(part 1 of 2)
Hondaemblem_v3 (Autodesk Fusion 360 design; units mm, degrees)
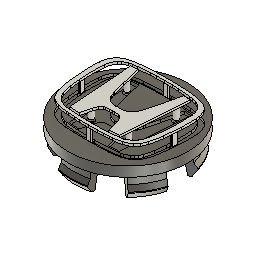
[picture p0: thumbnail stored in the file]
canvas "Ansichtsbereich"
sketch "Skizze1" plane through (0, 0, 0) normal (0, 0, 1) x axis (1, 0, 0)
  line L1 (14.7403, 16.2796) -> (11.3697, 16.5909)
  line L2 (9.2155, 7.0997) -> (11.3697, 16.5909)
  line L3 (7.6397, 1.1797) -> (9.2155, 7.0997)
  line L4 (7.4453, 0.4535) -> (7.6397, 1.1797)
  line L5 (1.2661, -4.9077) -> (0.003, -4.9077)
  line L6 (12.3974, -16.7274) -> (14.7403, 16.2796)
  line L7 (7.491, -17.0185) -> (12.3974, -16.7274)
  line L8 (1.2876, -7.8245) -> (0.011, -7.8245)
  line L9 (7.491, -17.0185) -> (6.1505, -11.8495)
  line L10 (0.011, -7.8245) -> (0.003, -4.9077)
  line L11 (1.489, -18.363) -> (0.0029, -18.3671)
  line L12 (1.489, -18.363) -> (0.0029, -18.3671)
  line L13 (1.7175, 19.8498) -> (-0.0237, 19.8498)
  line L14 (7.2522, -19.7275) -> (10.1907, -19.5091)
  line L15 (-7.418, -17.0597) -> (-6.1061, -11.8834)
  line L16 (-7.4689, 0.4122) -> (-7.6673, 1.1374)
  line L17 (-7.1642, -19.7674) -> (-10.1039, -19.5652)
  line L18 (-14.8513, 16.1978) -> (-11.4824, 16.5277)
  line L19 (-9.2758, 7.0486) -> (-11.4824, 16.5277)
  line L20 (-7.418, -17.0597) -> (-12.3259, -16.7957)
  line L21 (-7.6673, 1.1374) -> (-9.2758, 7.0486)
  line L22 (-12.3259, -16.7957) -> (-14.8513, 16.1978)
  line L23 (-1.4087, -18.371) -> (0.0774, -18.3669)
  line L24 (-1.2655, -7.8316) -> (0.011, -7.8245)
  line L25 (-1.2602, -4.9147) -> (0.003, -4.9077)
  line L26 (-1.8484, 19.84) -> (-0.1072, 19.8496)
  line L27 (-0.0665, -18.3673) -> (0.0774, -18.3669)
  line L28 (0.1112, -19.955) -> (-0.0002, -19.9555)
  line L29 (0, 18.41) -> (-0.123, 18.4097)
  line L30 (-0.1072, 19.8496) -> (-0.0237, 19.8498)
  line L31 (-0.0676, -17.9673) -> (0.0763, -17.9669)
  line L32 (1.2629, -4.7077) -> (0.0024, -4.7077)
  line L33 (7.2521, 0.5052) -> (7.4465, 1.2313)
  line L34 (7.4465, 1.2313) -> (9.0212, 7.1476)
  line L35 (9.0212, 7.1476) -> (11.2135, 16.8061)
  line L36 (14.9536, 16.4608) -> (11.2135, 16.8061)
  line L37 (12.5844, -16.9167) -> (14.9536, 16.4608)
  line L38 (7.3386, -17.2279) -> (12.5844, -16.9167)
  line L39 (7.3386, -17.2279) -> (5.9566, -11.8986)
  line L40 (1.2876, -8.0245) -> (0.0116, -8.0245)
  line L41 (-1.2644, -8.0316) -> (0.0116, -8.0245)
  line L42 (-7.2645, -17.2683) -> (-5.9119, -11.9314)
  line L43 (-7.2645, -17.2683) -> (-12.5119, -16.986)
  line L44 (-12.5119, -16.986) -> (-15.0656, 16.3778)
  line L45 (-15.0656, 16.3778) -> (-11.3274, 16.7438)
  line L46 (-9.0818, 7.0975) -> (-11.3274, 16.7438)
  line L47 (-7.4744, 1.1901) -> (-9.0818, 7.0975)
  line L48 (-7.276, 0.465) -> (-7.4744, 1.1901)
  line L49 (-1.258, -4.7147) -> (0.0024, -4.7077)
  line L50 (-0.066, -18.5673) -> (0.078, -18.5669)
  line L51 (0.0023, -18.1671) -> (0.0769, -18.1669)
  line L52 (-1.4092, -18.171) -> (0.0023, -18.1671)
  line L53 (-0.0028, 18.21) -> (-0.1191, 18.2097)
  line L54 (1.4884, -18.163) -> (0.0769, -18.1669)
  line L55 (7.267, -19.927) -> (10.2055, -19.7085)
  line L56 (1.7175, 20.0498) -> (-0.024, 20.0498)
  line L57 (-0.108, 20.0496) -> (-0.024, 20.0498)
  line L58 (-1.8495, 20.04) -> (-0.108, 20.0496)
  line L59 (-7.178, -19.9669) -> (-10.1176, -19.7647)
  arc A1 centre (-5.6033, 3.9463) radius 13.508 clockwise from (7.4453, 0.4535) to (6.6276, -1.787)
  arc A2 centre (1.7719, 0.4891) radius 5.3627 clockwise from (6.6276, -1.787) to (2.178, -4.8581)
  arc A3 centre (0.569, 16.3289) radius 21.248 clockwise from (2.178, -4.8581) to (1.2661, -4.9077)
  arc A4 centre (1.2876, -19.9561) radius 12.1316 clockwise from (1.2876, -7.8245) to (3.2582, -7.9857)
  arc A5 centre (2.9272, -9.9961) radius 2.0375 clockwise from (3.2582, -7.9857) to (4.0649, -8.3058)
  arc A6 centre (2.0068, -11.3638) radius 3.6861 clockwise from (4.0649, -8.3058) to (5.1675, -9.4672)
  arc A7 centre (-2.2698, -13.9299) radius 8.6734 clockwise from (5.1675, -9.4672) to (6.1505, -11.8495)
  arc A8 centre (1.224, 77.5099) radius 95.8732 clockwise from (13.5076, -17.5732) to (1.489, -18.363)
  arc A9 centre (12.7513, -11.7186) radius 5.9032 clockwise from (15.05, -17.1559) to (13.5076, -17.5732)
  arc A10 centre (8.9082, -2.6284) radius 15.7724 clockwise from (17.37, -15.9388) to (15.05, -17.1559)
  arc A11 centre (15.2799, -12.6511) radius 3.8959 clockwise from (18.3081, -15.1021) to (17.37, -15.9388)
  arc A12 centre (-1.4919, 0.9237) radius 25.4728 clockwise from (19.2556, -13.855) to (18.3081, -15.1021)
  arc A13 centre (14.4543, -10.4349) radius 5.8949 clockwise from (20.0596, -12.2596) to (19.2556, -13.855)
  arc A14 centre (-8.1428, -3.079) radius 29.659 clockwise from (21.1576, -7.6773) to (20.0596, -12.2596)
  arc A15 centre (-50.9109, 3.633) radius 72.9507 clockwise from (21.8058, -2.2052) to (21.1576, -7.6773)
  arc A16 centre (-55.8755, 4.0316) radius 77.9312 clockwise from (21.8058, 10.2685) to (21.8058, -2.2052)
  arc A17 centre (13.0733, 9.5674) radius 8.7605 clockwise from (19.9777, 14.9596) to (21.8058, 10.2685)
  arc A18 centre (16.9965, 12.6313) radius 3.7827 clockwise from (18.947, 15.8723) to (19.9777, 14.9596)
  arc A19 centre (12.8299, 5.7077) radius 11.8633 clockwise from (16.6863, 16.9267) to (18.947, 15.8723)
  arc A20 centre (3.8353, -18.6888) radius 37.0384 clockwise from (3.8143, 18.3497) to (6.8105, 18.23)
  arc A21 centre (13.0764, 6.4248) radius 11.105 clockwise from (15.0535, 17.3524) to (16.6863, 16.9267)
  arc A22 centre (8.3657, -19.6124) radius 37.5649 clockwise from (12.8326, 17.686) to (15.0535, 17.3524)
  arc A23 centre (0.4785, -85.4698) radius 103.8929 clockwise from (6.8105, 18.23) to (12.8326, 17.686)
  arc A24 centre (3.7437, 142.9454) radius 124.5958 clockwise from (3.8143, 18.3497) to (-0.123, 18.4097)
  arc A25 centre (13.0733, 9.5674) radius 8.7605 clockwise from (19.9777, 14.9596) to (21.8058, 10.2685)
  arc A26 centre (8.9082, -2.6284) radius 15.7724 clockwise from (17.37, -15.9388) to (15.05, -17.1559)
  arc A27 centre (16.9965, 12.6313) radius 3.7827 clockwise from (18.947, 15.8723) to (19.9777, 14.9596)
  arc A28 centre (12.8299, 5.7077) radius 11.8633 clockwise from (16.6863, 16.9267) to (18.947, 15.8723)
  arc A29 centre (13.0764, 6.4248) radius 11.105 clockwise from (15.0535, 17.3524) to (16.6863, 16.9267)
  arc A30 centre (-55.8755, 4.0316) radius 77.9312 clockwise from (21.8058, 10.2685) to (21.8058, -2.2052)
  arc A31 centre (15.2799, -12.6511) radius 3.8959 clockwise from (18.3081, -15.1021) to (17.37, -15.9388)
  arc A32 centre (-8.1428, -3.079) radius 29.659 clockwise from (21.1576, -7.6773) to (20.0596, -12.2596)
  arc A33 centre (-50.9109, 3.633) radius 72.9507 clockwise from (21.8058, -2.2052) to (21.1576, -7.6773)
  arc A34 centre (-1.4919, 0.9237) radius 25.4728 clockwise from (19.2556, -13.855) to (18.3081, -15.1021)
  arc A35 centre (14.4543, -10.4349) radius 5.8949 clockwise from (20.0596, -12.2596) to (19.2556, -13.855)
  arc A36 centre (12.7513, -11.7186) radius 5.9032 clockwise from (15.05, -17.1559) to (13.5076, -17.5732)
  arc A37 centre (1.224, 77.5099) radius 95.8732 clockwise from (13.5076, -17.5732) to (1.489, -18.363)
  arc A38 centre (8.3657, -19.6124) radius 37.5649 clockwise from (12.8326, 17.686) to (15.0535, 17.3524)
  arc A39 centre (0.4785, -85.4698) radius 103.8929 clockwise from (6.8745, 18.2261) to (12.8326, 17.686)
  arc A40 centre (3.8353, -18.6888) radius 37.0397 clockwise from (3.8353, 18.351) to (6.8745, 18.2261)
  arc A41 centre (3.8353, 142.9437) radius 124.5927 clockwise from (3.8353, 18.351) to (0, 18.41)
  arc A42 centre (1.7175, -96.317) radius 116.1669 clockwise from (1.7175, 19.8498) to (11.6229, 19.4267)
  arc A43 centre (7.8992, -24.0836) radius 43.6694 clockwise from (11.6229, 19.4267) to (17.105, 18.6044)
  arc A44 centre (14.7144, 7.5187) radius 11.3406 clockwise from (17.105, 18.6044) to (21.4708, 16.6269)
  arc A45 centre (19.0969, 13.4267) radius 3.9846 clockwise from (21.4708, 16.6269) to (22.4141, 15.6341)
  arc A46 centre (12.4351, 8.9937) radius 11.9865 clockwise from (22.4141, 15.6341) to (24.1926, 11.3252)
  arc A47 centre (14.2774, 9.359) radius 10.1083 clockwise from (24.1926, 11.3252) to (24.3555, 10.1404)
  arc A48 centre (-27.9737, 6.0834) radius 52.4862 clockwise from (24.3555, 10.1404) to (24.373, 2.259)
  arc A49 centre (-312.3688, 26.8612) radius 337.6393 clockwise from (24.373, 2.259) to (23.6781, -5.8921)
  arc A50 centre (-7.6057, -2.843) radius 31.432 clockwise from (23.6781, -5.8921) to (22.3695, -12.3014)
  arc A51 centre (6.3134, -7.2351) radius 16.8364 clockwise from (22.3695, -12.3014) to (21.3014, -14.9047)
  arc A52 centre (16.2941, -12.3424) radius 5.6248 clockwise from (21.3014, -14.9047) to (19.4858, -16.974)
  arc A53 centre (12.2327, -6.4486) radius 12.7824 clockwise from (19.4858, -16.974) to (15.8012, -18.7229)
  arc A54 centre (10.7069, -1.2005) radius 18.2479 clockwise from (15.8012, -18.7229) to (11.5158, -19.4304)
  arc A55 centre (13.486, -63.8389) radius 44.4521 clockwise from (10.1907, -19.5091) to (11.5158, -19.4304)
  arc A56 centre (2.7253, 41.1689) radius 61.0644 clockwise from (7.2522, -19.7275) to (4.4477, -19.8712)
  arc A57 centre (-2.435, 224.0452) radius 244.0136 clockwise from (4.4477, -19.8712) to (0.0029, -19.9561)
  arc A58 centre (-14.4176, -10.5147) radius 5.8949 clockwise from (-19.1999, -13.9613) to (-20.0127, -12.3704)
  arc A59 centre (-3.7531, -18.7097) radius 37.0384 clockwise from (-6.9324, 18.192) to (-3.9369, 18.3282)
  arc A60 centre (-17.0873, 12.5371) radius 3.7827 clockwise from (-20.0813, 14.8488) to (-19.0556, 15.7673)
  arc A61 centre (-0.0273, -85.4712) radius 103.8929 clockwise from (-12.9514, 17.6147) to (-6.9964, 18.1877)
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  point P261 (-0.0665, -18.3673)
  point P263 (0.1112, -19.955)
  tangent L4 A1
  tangent A1 A2
  horizontal L5
  tangent A2 A3
  horizontal L8
  tangent L8 A4
  tangent A4 A5
  tangent A5 A6
  tangent A6 A7
  perpendicular L10 L11
  tangent L11 A8
  tangent A8 A9
  tangent A9 A10
  tangent A10 A11
  tangent A11 A12
  tangent A12 A13
  tangent A13 A14
  tangent A14 A15
  tangent A15 A16
  tangent A16 A17
  tangent A17 A18
  tangent A18 A19
  tangent A19 A21
  tangent A21 A22
  tangent A22 A23
  tangent A20 A24
  tangent A37 L12
  tangent A36 A37
  tangent A26 A36
  tangent A26 A31
  tangent A31 A34
  tangent A34 A35
  tangent A32 A35
  tangent A32 A33
  tangent A30 A33
  tangent A25 A30
  tangent A25 A27
  tangent A27 A28
  tangent A28 A29
  tangent A29 A38
  tangent A38 A39
  tangent A40 A41
  horizontal L13
  tangent L13 A42
  tangent A42 A43
  tangent A43 A44
  tangent A44 A45
  tangent A45 A46
  tangent A46 A47
  tangent A47 A48
  tangent A48 A49
  tangent A49 A50
  tangent A50 A51
  tangent A51 A52
  tangent A52 A53
  tangent A53 A54
  tangent A54 A55
  tangent L14 A56
  tangent A56 A57
  coincident L23 P261
  coincident A57 P263
  parallel L27 L31
  parallel L27 L50
  parallel L23 L51
  parallel L23 L52
  parallel L29 L53
  parallel L12 L54
  dimension "d174" = -0.2
  dimension "d176" = 0.2
  dimension "d177" = 0.2
  dimension "d178" = 0.2
extrude "Extrusion1" new body sketch "Skizze1" along normal blind 2
sketch "Skizze2" plane through (0, 0, 0) normal (0, 0, 1) x axis (1, 0, 0)
  circle C1 centre (0, 0) radius 30
  circle C2 centre (0, 0) radius 29
  point P1 (0, 0)
  point P2 (0, 0)
  coincident P1 P2
  concentric C1 C2
  dimension "d3" diameter C1 = 60
  dimension "d11" diameter C2 = 58
extrude "Extrusion4" add sketch "Skizze2" along normal blind 1
extrude "Extrusion5" add sketch "Skizze2" along normal blind 2
extrude "Extrusion6" cut of existing geometry blind -1
sketch "Skizze4" plane through (0, 0, 1) normal (0, 0, 1) x axis (-1, 0, 0)
  line L1 (-7.2522, 19.7275) -> (-10.1907, 19.5091)
  line L2 (0.0002, 19.9555) -> (-0.1112, 19.955)
  line L3 (10.1039, 19.5652) -> (7.1642, 19.7674)
  line L4 (0.1072, -19.8496) -> (1.8484, -19.84)
  line L5 (0.0237, -19.8498) -> (0.1072, -19.8496)
  line L6 (-1.7175, -19.8498) -> (0.0237, -19.8498)
  circle C1 centre (0, 0) radius 30
  arc A1 centre (-13.486, 63.8389) radius 44.4521 clockwise from (-10.1907, 19.5091) to (-11.5158, 19.4304)
  arc A2 centre (-2.7253, -41.1689) radius 61.0644 clockwise from (-7.2522, 19.7275) to (-4.4477, 19.8712)
  arc A3 centre (2.435, -224.0452) radius 244.0136 clockwise from (-4.4477, 19.8712) to (-0.1112, 19.955)
  arc A4 centre (-1.1752, -224.0552) radius 244.0136 clockwise from (0.0002, 19.9555) to (4.359, 19.8956)
  arc A5 centre (2.974, -41.1531) radius 61.0644 clockwise from (4.359, 19.8956) to (7.1642, 19.7674)
  arc A6 centre (13.1541, 63.9125) radius 44.4521 clockwise from (11.4294, 19.4939) to (10.1039, 19.5652)
  arc A7 centre (10.7214, 1.2597) radius 18.2479 clockwise from (11.4294, 19.4939) to (15.7186, 18.81)
  arc A8 centre (12.2181, 6.5162) radius 12.7824 clockwise from (15.7186, 18.81) to (19.4129, 17.0815)
  arc A9 centre (16.2469, 12.4323) radius 5.6248 clockwise from (19.4129, 17.0815) to (21.2399, 15.0223)
  arc A10 centre (6.2945, 7.2699) radius 16.8364 clockwise from (21.2399, 15.0223) to (22.3223, 12.425)
  arc A11 centre (-7.6001, 2.801) radius 31.432 clockwise from (22.3223, 12.425) to (23.6664, 6.023)
  arc A12 centre (-312.1943, -28.5875) radius 337.6393 clockwise from (23.6664, 6.023) to (24.4063, -2.1242)
  arc A13 centre (-27.9185, -6.2379) radius 52.4862 clockwise from (24.4063, -2.1242) to (24.4324, -10.0055)
  arc A14 centre (14.3501, -9.2799) radius 10.1083 clockwise from (24.4324, -10.0055) to (24.2761, -11.1912)
  arc A15 centre (12.5058, -8.9248) radius 11.9865 clockwise from (24.2761, -11.1912) to (22.5214, -15.5099)
  arc A16 centre (19.192, -13.3209) radius 3.9846 clockwise from (22.5214, -15.5099) to (21.5836, -16.5079)
  arc A17 centre (14.7769, -7.4372) radius 11.3406 clockwise from (21.5836, -16.5079) to (17.2288, -18.5095)
  arc A18 centre (7.7872, 24.127) radius 43.6694 clockwise from (17.2288, -18.5095) to (11.7513, -19.3621)
  arc A19 centre (1.2062, 96.3251) radius 116.1669 clockwise from (11.7513, -19.3621) to (1.8484, -19.84)
  arc A20 centre (-1.7175, 96.317) radius 116.1669 clockwise from (-1.7175, -19.8498) to (-11.6229, -19.4267)
  arc A21 centre (-7.8992, 24.0836) radius 43.6694 clockwise from (-11.6229, -19.4267) to (-17.105, -18.6044)
  arc A22 centre (-14.7144, -7.5187) radius 11.3406 clockwise from (-17.105, -18.6044) to (-21.4708, -16.6269)
  arc A23 centre (-19.0969, -13.4267) radius 3.9846 clockwise from (-21.4708, -16.6269) to (-22.4141, -15.6341)
  arc A24 centre (-12.4351, -8.9937) radius 11.9865 clockwise from (-22.4141, -15.6341) to (-24.1926, -11.3252)
  arc A25 centre (-14.2774, -9.359) radius 10.1083 clockwise from (-24.1926, -11.3252) to (-24.3555, -10.1404)
  arc A26 centre (27.9737, -6.0834) radius 52.4862 clockwise from (-24.3555, -10.1404) to (-24.373, -2.259)
  arc A27 centre (312.3688, -26.8612) radius 337.6393 clockwise from (-24.373, -2.259) to (-23.6781, 5.8921)
  arc A28 centre (7.6057, 2.843) radius 31.432 clockwise from (-23.6781, 5.8921) to (-22.3695, 12.3014)
  arc A29 centre (-6.3134, 7.2351) radius 16.8364 clockwise from (-22.3695, 12.3014) to (-21.3014, 14.9047)
  arc A30 centre (-16.2941, 12.3424) radius 5.6248 clockwise from (-21.3014, 14.9047) to (-19.4858, 16.974)
  arc A31 centre (-12.2327, 6.4486) radius 12.7824 clockwise from (-19.4858, 16.974) to (-15.8012, 18.7229)
  arc A32 centre (-10.7069, 1.2005) radius 18.2479 clockwise from (-15.8012, 18.7229) to (-11.5158, 19.4304)
  circle C2 centre (0, 0) radius 29.1
  concentric C1 C2
  dimension "d23" diameter C2 = 58.2
extrude "Extrusion9" cut sketch "Skizze4" profile of C1 C2 against normal blind 1
extrude "Extrusion10" add sketch "Skizze2" along normal blind 1
sketch "Skizze5" plane through (0, 0, 0) normal (0, 0, -1) x axis (1, 0, 0)
  line L1 (-26, 0) -> (-27, 0)
  line L2 (-29.6, 0) -> (-26, 0)
  line L3 (-26, 7.2801) -> (-26, 0)
  line L4 (-26, -7.2801) -> (-26, 0)
  line L5 (-34, -7.2801) -> (-26, -7.2801)
  line L6 (-34, 7.2801) -> (-26, 7.2801)
  line L7 (0, -12) -> (0, 0)
  line L8 (0, 0) -> (0, -12)
  line L9 (0, 0) -> (12, 0)
  line L10 (11, -11) -> (0, 0)
  line L11 (-8.2916, -8.2916) -> (0, 0)
  line L12 (34, 7.2801) -> (26, 7.2801)
  line L13 (26, 7.2801) -> (26, 0)
  line L14 (26, -7.2801) -> (26, 0)
  line L15 (34, -7.2801) -> (26, -7.2801)
  line L16 (-7.2801, -34) -> (-7.2801, -26)
  line L17 (-7.2801, -26) -> (0, -26)
  line L18 (7.2801, -26) -> (0, -26)
  line L19 (7.2801, -34) -> (7.2801, -26)
  line L20 (-7.2801, 34) -> (-7.2801, 26)
  line L21 (-7.2801, 26) -> (0, 26)
  line L22 (7.2801, 34) -> (7.2801, 26)
  line L23 (7.2801, 26) -> (0, 26)
  line L24 (-18.8938, -29.1894) -> (-13.237, -23.5326)
  line L25 (-13.237, -23.5326) -> (-18.3848, -18.3848)
  line L26 (-29.1894, -18.8938) -> (-23.5326, -13.237)
  line L27 (-23.5326, -13.237) -> (-18.3848, -18.3848)
  line L28 (29.1894, -18.8938) -> (23.5326, -13.237)
  line L29 (23.5326, -13.237) -> (18.3848, -18.3848)
  line L30 (18.8938, -29.1894) -> (13.237, -23.5326)
  line L31 (13.237, -23.5326) -> (18.3848, -18.3848)
  line L32 (-18.8938, 29.1894) -> (-13.237, 23.5326)
  line L33 (-13.237, 23.5326) -> (-18.3848, 18.3848)
  line L34 (-29.1894, 18.8938) -> (-23.5326, 13.237)
  line L35 (-23.5326, 13.237) -> (-18.3848, 18.3848)
  line L36 (29.1894, 18.8938) -> (23.5326, 13.237)
  line L37 (23.5326, 13.237) -> (18.3848, 18.3848)
  line L38 (18.8938, 29.1894) -> (13.237, 23.5326)
  line L39 (13.237, 23.5326) -> (18.3848, 18.3848)
  circle C1 centre (0, 0) radius 30
  circle C2 centre (0, 0) radius 27
  circle C3 centre (0, 0) radius 27.7
  circle C4 centre (0, 0) radius 29.6
  circle C5 centre (0, 0) radius 28
  point P5 (-27, 0)
  point P8 (-26, 7.2801)
  point P9 (-26, -7.2801)
  point P7 (-29.6, 0)
  point P13 (0, 0)
  point P14 (0, 0)
  point P12 (0, 0)
  point P16 (0, 0)
  point P3 (0, 0)
  point P18 (0, 0)
  point P20 (0, 0)
  point P6 (-26, 0)
  point P24 (26, 0)
  point P22 (26, 7.2801)
  point P25 (26, -7.2801)
  point P10 (-34, -7.2801)
  point P26 (34, -7.2801)
  point P11 (-34, 7.2801)
  point P23 (34, 7.2801)
  point P34 (0, 26)
  point P32 (-7.2801, 26)
  point P35 (7.2801, 26)
  point P36 (7.2801, 34)
  point P33 (-7.2801, 34)
  point P27 (-7.2801, -26)
  point P28 (-7.2801, -34)
  point P29 (0, -26)
  point P30 (7.2801, -26)
  point P31 (7.2801, -34)
  concentric C1 C2
  coincident C2 P5
  horizontal L1
  coincident C2 P8
  perpendicular L1 L3
  coincident C2 P9
  perpendicular L1 L4
  perpendicular L4 L5
  perpendicular L3 L6
  concentric C2 C4
  coincident P7 C4
  concentric C4 C5
  coincident P13 P14
  vertical L7
  coincident P12 P16
  parallel L7 L8
  perpendicular L7 L9
  coincident P3 P18
  coincident P3 P20
  perpendicular L10 L11
  symmetric P6 L8 P24
  symmetric P8 L8 P22
  symmetric P9 L8 P25
  symmetric P10 L8 P26
  symmetric P11 L8 P23
  symmetric P6 L10 P34
  symmetric P8 L10 P32
  symmetric P9 L10 P35
  symmetric P10 L10 P36
  symmetric P11 L10 P33
  symmetric L10 P22 P27
  symmetric L10 P23 P28
  symmetric L10 P24 P29
  symmetric L10 P25 P30
  symmetric L10 P26 P31
  perpendicular L34 L35
  perpendicular L32 L33
  dimension "d33" diameter C2 = 54
  dimension "d35" diameter C3 = 55.4 (= "53.000 mm + 2.4 mm")
  dimension "d36" distance P5 P6 = 1
  dimension "d37" distance P6 P7 = 3.6
  dimension "d38" diameter C5 = 56
extrude "Extrusion11" add sketch "Skizze5" profile of C2 C3 L3 L4 L5 L6 C5 L12 L13 L14 L15 L16 L17 L18 L19 L20 L21 L22 L23 L24 L25 L26 L27 L28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 along normal blind 4.6
extrude "Extrusion12" sketch "Skizze5" profile of C2 C3 L3 L4 L5 L6 C4 C5 L12 L13 L14 L15 L16 L17 L18 L19 L20 L21 L22 L23 L24 L25 L26 L27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 blind 5
sketch "Skizze6" plane through (0, -7.2801, 0) normal (0, -1, 0) x axis (1, 0, 0)
  line L1 (-27.037, 0) -> (-26, 0)
  line L2 (-27.037, -4.6) -> (-27.037, 0)
  line L3 (-28.6908, -4.6) -> (-27.037, -4.6)
  line L4 (-28.6908, -9.6) -> (-28.6908, -4.6)
  line L5 (-26, -9.6) -> (-28.6908, -9.6)
  line L6 (-26, 0) -> (-26, -9.6)
  line L7 (-28.5813, -7.2655) -> (-27.037, -9.6)
  line L8 (-27.037, -4.6) -> (-28.5813, -6.9345)
  line L9 (-27.037, -9.6) -> (-26, -9.6)
  line L10 (-26, -4.6) -> (-27.037, -4.6)
  line L11 (-26, -9.6) -> (-26, -4.6)
  arc A1 centre (-28.3311, -7.1) radius 0.3 clockwise from (-28.5813, -7.2655) to (-28.5813, -6.9345)
  point P4 (-27.037, -4.6)
  point P8 (-27.037, -4.6)
  point P12 (-27.037, -4.6)
  point P7 (-26, -9.6)
  point P10 (-26, -9.6)
  coincident P4 P8
  horizontal L9
  horizontal L10
  vertical L11
  coincident P4 P12
  coincident P7 P10
  tangent L7 A1
  tangent L8 A1
  dimension "d44" radius A1 = 0.3
chamfer "Fase1" distance 1.6 Rotate Angle 57.5
chamfer "Fase2" distance 1.6 Rotate Angle 57
delete_face "Fläche löschen2"
fillet "Abrundung2" radius 0.4
work_plane "Arbeitsebene1" AlongDistance 0
split "Teilen1" bodies "Emblem"
move "Verschieben1"
extrude "Extrusion13" add of existing geometry blind 2
sketch "Skizze8" plane through (0, 0, -2) normal (0, 0, -1) x axis (1, 0, 0)
  circle C1 centre (0, 0) radius 30
  circle C2 centre (0, 0) radius 27
  circle C3 centre (0, 0) radius 28
  point P1 (0, 0)
  point P4 (0, 0)
  coincident P1 P4
fillet "Abrundung3" radius 0.4
combine "Kombinieren1"
extrude "Extrusion14" add of existing geometry blind 1
extrude "Extrusion16" add of existing geometry blind 1
extrude "Extrusion17" add of existing geometry blind 1
extrude "Extrusion18" add of existing geometry blind 1
extrude "Extrusion19" add of existing geometry blind 1
extrude "Extrusion20" add of existing geometry blind 1
work_plane "Arbeitsebene2" AlongDistance 0
split "Teilen2" bodies "Emblem (1)", "Emblem (2)", "Emblem (3)", "Emblem (4)", "Emblem (5)", "Emblem (6)", "Emblem (7)", "Emblem (8)"
sketch "Skizze9" plane through (0, 0, -2) normal (0, 0, -1) x axis (1, 0, 0)
  line L1 (0, 30) -> (0, 0)
  line L2 (25.9808, 15) -> (0, 0)
  line L3 (25.9808, -15) -> (0, 0)
  line L4 (0, -30) -> (0, 0)
  line L5 (-25.9808, -15) -> (0, 0)
  line L6 (-25.9808, 15) -> (0, 0)
  circle C1 centre (0, 0) radius 30
  circle C2 centre (0, 0) radius 30
  circle C3 centre (0, 0) radius 30
  point P1 (0, 0)
  point P3 (0, 0)
  point P4 (0, 0)
  point P5 (0, 0)
  point P6 (0, 30)
  point P7 (0, 0)
  point P8 (25.9808, 15)
  point P9 (0, 0)
  point P10 (25.9808, -15)
  point P11 (0, 0)
  point P12 (0, -30)
  point P15 (0, 0)
  point P16 (-25.9808, 15)
  point P13 (0, 0)
  point P14 (-25.9808, -15)
  coincident P1 P3
  coincident P1 P4
  coincident P4 P5
  coincident C2 P6
  vertical L1
  coincident P1 P7
  coincident C3 P8
  coincident P4 P9
  coincident C3 P10
  coincident P3 P11
  coincident C3 P12
  parallel L1 L4
  symmetric L1 P7 P15
  symmetric L1 P8 P16
  symmetric L1 P9 P13
  symmetric L1 P10 P14
  dimension "d72" angle L1 L2 = 60
  dimension "d73" angle L2 L3 = 60
move "Verschieben2"
copy_paste_bodies "Körper kopieren/einfügen"
move "Verschieben3"
combine "Kombinieren2" bodies "Emblem (6) (1)", "Emblem (2)", "Emblem (5)", "Emblem (6)", "Emblem (7)", "Emblem"
chamfer "Fase3" distance 3
sketch "Skizze10" plane through (0, 0, 2) normal (0, 0, 1) x axis (-1, 0, 0)
  line L1 (-0.003, 4.9077) -> (-1.2661, 4.9077)
  line L2 (1.2602, 4.9147) -> (-0.003, 4.9077)
  line L3 (7.6673, -1.1374) -> (7.4689, -0.4122)
  line L4 (9.2758, -7.0486) -> (7.6673, -1.1374)
  line L5 (11.4824, -16.5277) -> (9.2758, -7.0486)
  line L6 (14.8513, -16.1978) -> (11.4824, -16.5277)
  line L7 (12.3259, 16.7957) -> (14.8513, -16.1978)
  line L8 (7.418, 17.0597) -> (12.3259, 16.7957)
  line L9 (6.1061, 11.8834) -> (7.418, 17.0597)
  line L10 (-0.011, 7.8245) -> (1.2655, 7.8316)
  line L11 (-1.2876, 7.8245) -> (-0.011, 7.8245)
  line L12 (-7.491, 17.0185) -> (-6.1505, 11.8495)
  line L13 (-12.3974, 16.7274) -> (-7.491, 17.0185)
  line L14 (-14.7403, -16.2796) -> (-12.3974, 16.7274)
  line L15 (-11.3697, -16.5909) -> (-14.7403, -16.2796)
  line L16 (-9.2155, -7.0997) -> (-11.3697, -16.5909)
  line L17 (-7.6397, -1.1797) -> (-9.2155, -7.0997)
  line L18 (-7.4453, -0.4535) -> (-7.6397, -1.1797)
  line L19 (9.5555, 3.6264) -> (13.1668, -16.3628)
  line L20 (-0.011, 7.8245) -> (-0.003, 4.9077)
  line L21 (9, 3) -> (9.8719, 16.9277)
  arc A1 centre (0.6805, -16.3254) radius 21.248 clockwise from (1.2602, 4.9147) to (2.1723, 4.8702)
  arc A2 centre (1.7958, -0.4793) radius 5.3627 clockwise from (2.1723, 4.8702) to (6.6388, 1.8237)
  arc A3 centre (-5.5602, -3.9771) radius 13.508 clockwise from (6.6388, 1.8237) to (7.4689, -0.4122)
  arc A4 centre (-2.3255, 13.9172) radius 8.6734 clockwise from (6.1061, 11.8834) to (5.1363, 9.4957)
  arc A5 centre (1.9651, 11.3748) radius 3.6861 clockwise from (5.1363, 9.4957) to (4.0401, 8.3282)
  arc A6 centre (2.8931, 10.0122) radius 2.0375 clockwise from (4.0401, 8.3282) to (3.2352, 8.0036)
  arc A7 centre (1.1985, 19.963) radius 12.1316 clockwise from (3.2352, 8.0036) to (1.2655, 7.8316)
  arc A8 centre (-1.2876, 19.9561) radius 12.1316 clockwise from (-1.2876, 7.8245) to (-3.2582, 7.9857)
  arc A9 centre (-2.9272, 9.9961) radius 2.0375 clockwise from (-3.2582, 7.9857) to (-4.0649, 8.3058)
  arc A10 centre (-2.0068, 11.3638) radius 3.6861 clockwise from (-4.0649, 8.3058) to (-5.1675, 9.4672)
  arc A11 centre (2.2698, 13.9299) radius 8.6734 clockwise from (-5.1675, 9.4672) to (-6.1505, 11.8495)
  arc A12 centre (5.6033, -3.9463) radius 13.508 clockwise from (-7.4453, -0.4535) to (-6.6276, 1.787)
  arc A13 centre (-1.7719, -0.4891) radius 5.3627 clockwise from (-6.6276, 1.787) to (-2.178, 4.8581)
  arc A14 centre (-0.569, -16.3289) radius 21.248 clockwise from (-2.178, 4.8581) to (-1.2661, 4.9077)
  circle C1 centre (12.3393, -11.7822) radius 1.2
  circle C2 centre (9.3758, 9.0032) radius 1.2
  circle C3 centre (-9.4042, 8.9513) radius 1.2
  circle C4 centre (-12.2528, -11.8501) radius 1.2
  circle C5 centre (12.3393, -11.7822) radius 1.6
  circle C6 centre (9.3758, 9.0032) radius 1.6
  circle C7 centre (-9.4042, 8.9513) radius 1.6
  circle C8 centre (-12.2528, -11.8501) radius 1.6
  point P48 (13.1668, -16.3628)
  point P50 (12.3393, -11.7822)
  point P3 (-0.003, 4.9077)
  point P51 (-0.003, 4.9077)
  point P26 (-0.011, 7.8245)
  point P52 (-0.011, 7.8245)
  point P53 (9.8719, 16.9277)
  point P55 (9.3758, 9.0032)
  midpoint L6 P48
  coincident L19 P50
  coincident P3 P51
  coincident P26 P52
  midpoint L8 P53
  coincident L21 P55
  symmetric C1 L20 C4
  symmetric L20 C2 C3
  symmetric L20 C5 C8
  symmetric L20 C6 C7
  dimension "d75" diameter C1 = 2.4
  dimension "d76" diameter C2 = 2.4
  dimension "d82" = 0.4
  dimension "d83" = 0.4
delete_face "Fläche löschen3"
sketch "Skizze11" plane through (0, 0, 2) normal (0, 0, 1) x axis (-1, 0, 0)
  line L1 (0, -18.41) -> (0.123, -18.4097)
  line L2 (1.4087, 18.371) -> (-1.489, 18.363)
  line L3 (0.0237, -19.8498) -> (-1.7175, -19.8498)
  line L4 (0.1072, -19.8496) -> (0.0237, -19.8498)
  line L5 (1.8484, -19.84) -> (0.1072, -19.8496)
  line L6 (7.1642, 19.7674) -> (10.1039, 19.5652)
  line L7 (-0.1112, 19.955) -> (0.0002, 19.9555)
  line L8 (-10.1907, 19.5091) -> (-7.2522, 19.7275)
  line L9 (-24.2003, 0) -> (24.2325, 0)
  line L10 (29.0615, 0) -> (0, 0)
  line L11 (1.5038, 19.2297) -> (1.5038, 19.0297)
  line L12 (0.0038, 17.7) -> (0.0038, 18.6297)
  line L13 (-1.4962, 19.2297) -> (-1.4962, 19.0297)
  line L14 (-0.1962, 19.8297) -> (1.3038, 19.8297)
  line L15 (-1.0962, 18.6297) -> (1.1038, 18.6297)
  line L16 (1.1038, 19.6297) -> (-1.0962, 19.6297)
  line L17 (-1.5038, -19.2297) -> (-1.5038, -19.0297)
  line L18 (1.0962, -18.6297) -> (-1.1038, -18.6297)
  line L19 (1.4962, -19.2297) -> (1.4962, -19.0297)
  line L20 (-1.1038, -19.6297) -> (1.0962, -19.6297)
  line L21 (23.3108, -1.4905) -> (23.1113, -1.5045)
  line L22 (22.5309, 1.0613) -> (22.6843, -1.1334)
  line L23 (23.1015, 1.5022) -> (22.902, 1.4882)
  line L24 (23.6819, -1.0636) -> (23.5284, 1.131)
  line L25 (-22.8677, 1.4367) -> (-23.0672, 1.4506)
  line L26 (-22.65, -1.1849) -> (-22.4965, 1.0098)
  line L27 (-23.0769, -1.556) -> (-23.2764, -1.542)
  line L28 (-23.4941, 1.0795) -> (-23.6476, -1.1151)
  line L29 (1.9038, 19.1297) -> (1.5038, 19.1297)
  line L30 (-1.8962, 19.1297) -> (-1.6962, 19.1297)
  line L31 (0.003, 20.0296) -> (0.0038, 19.8297)
  line L32 (0.0038, 18.2297) -> (0.0038, 18.4297)
  line L33 (1.1038, 20.0297) -> (-1.0962, 20.0297)
  line L34 (-1.8962, 19.2297) -> (-1.8962, 19.0297)
  line L35 (-1.0962, 18.2297) -> (1.1038, 18.2297)
  line L36 (1.9038, 19.2297) -> (1.9038, 19.0297)
  line L37 (-1.8962, 19.2297) -> (-1.8962, 19.0297)
  line L38 (1.1038, 20.0297) -> (-1.0962, 20.0297)
  line L39 (1.9038, 19.2297) -> (1.9038, 19.0297)
  line L40 (-1.0962, 18.2297) -> (1.1038, 18.2297)
  line L41 (-1.8962, 19.2297) -> (-1.8962, 19.0297)
  line L42 (1.1038, 20.0297) -> (-1.0962, 20.0297)
  line L43 (1.9038, 19.2297) -> (1.9038, 19.0297)
  line L44 (-1.0962, 18.2297) -> (1.1038, 18.2297)
  line L45 (1.8962, -19.1297) -> (1.6962, -19.1297)
  line L46 (-0.0038, -18.2297) -> (-0.0038, -18.4297)
  line L47 (-1.8962, -19.0303) -> (-1.8962, -19.2303)
  line L48 (1.1038, -18.2303) -> (-1.0962, -18.2303)
  line L49 (1.9038, -19.0303) -> (1.9038, -19.2303)
  line L50 (-1.0962, -20.0303) -> (1.1038, -20.0303)
  line L51 (-1.8962, 19.2297) -> (-1.8962, 19.0297)
  line L52 (1.1038, 20.0297) -> (-1.0962, 20.0297)
  line L53 (1.9038, 19.2297) -> (1.9038, 19.0297)
  line L54 (-1.0962, 18.2297) -> (1.1038, 18.2297)
  line L55 (-22.8404, 1.8348) -> (-23.0399, 1.8488)
  line L56 (-22.2516, -1.2137) -> (-22.0982, 0.9809)
  line L57 (-23.1055, -1.9559) -> (-23.305, -1.942)
  line L58 (-23.8938, 1.1065) -> (-24.0472, -1.0881)
  line L59 (-22.1802, -0.201) -> (-22.3797, -0.187)
  line L60 (-22.9395, 1.8427) -> (-22.9535, 1.6432)
  line L61 (-23.1055, -1.9559) -> (-23.305, -1.942)
  line L62 (-23.8938, 1.1065) -> (-24.0472, -1.0881)
  line L63 (-22.8404, 1.8348) -> (-23.0399, 1.8488)
  line L64 (-22.2516, -1.2137) -> (-22.0982, 0.9809)
  line L65 (23.2389, -1.8965) -> (23.225, -1.697)
  line L66 (22.1852, 0.2706) -> (22.3847, 0.2845)
  line L67 (23.347, -1.8887) -> (23.1475, -1.9026)
  line L68 (22.1402, 1.0343) -> (22.2936, -1.1604)
  line L69 (23.0819, 1.9021) -> (22.8824, 1.8881)
  line L70 (24.0893, -1.0348) -> (23.9358, 1.1598)
  arc A1 centre (3.7531, 18.7097) radius 37.0397 clockwise from (6.9964, -18.1877) to (3.9579, -18.3294)
  arc A2 centre (4.6466, -142.9202) radius 124.5927 clockwise from (0.123, -18.4097) to (3.9579, -18.3294)
  arc A3 centre (-3.8353, -142.9437) radius 124.5927 clockwise from (-3.8353, -18.351) to (0, -18.41)
  arc A4 centre (-3.8353, 18.6888) radius 37.0397 clockwise from (-3.8353, -18.351) to (-6.8745, -18.2261)
  arc A5 centre (-0.4785, 85.4698) radius 103.8929 clockwise from (-6.8745, -18.2261) to (-12.8326, -17.686)
  arc A6 centre (-8.3657, 19.6124) radius 37.5649 clockwise from (-12.8326, -17.686) to (-15.0535, -17.3524)
  arc A7 centre (-13.0764, -6.4248) radius 11.105 clockwise from (-15.0535, -17.3524) to (-16.6863, -16.9267)
  arc A8 centre (-12.8299, -5.7077) radius 11.8633 clockwise from (-16.6863, -16.9267) to (-18.947, -15.8723)
  arc A9 centre (-16.9965, -12.6313) radius 3.7827 clockwise from (-18.947, -15.8723) to (-19.9777, -14.9596)
  arc A10 centre (-13.0733, -9.5674) radius 8.7605 clockwise from (-19.9777, -14.9596) to (-21.8058, -10.2685)
  arc A11 centre (55.8755, -4.0316) radius 77.9312 clockwise from (-21.8058, -10.2685) to (-21.8058, 2.2052)
  arc A12 centre (50.9109, -3.633) radius 72.9507 clockwise from (-21.8058, 2.2052) to (-21.1576, 7.6773)
  arc A13 centre (8.1428, 3.079) radius 29.659 clockwise from (-21.1576, 7.6773) to (-20.0596, 12.2596)
  arc A14 centre (-14.4543, 10.4349) radius 5.8949 clockwise from (-20.0596, 12.2596) to (-19.2556, 13.855)
  arc A15 centre (1.4919, -0.9237) radius 25.4728 clockwise from (-19.2556, 13.855) to (-18.3081, 15.1021)
  arc A16 centre (-15.2799, 12.6511) radius 3.8959 clockwise from (-18.3081, 15.1021) to (-17.37, 15.9388)
  arc A17 centre (-8.9082, 2.6284) radius 15.7724 clockwise from (-17.37, 15.9388) to (-15.05, 17.1559)
  arc A18 centre (-12.7513, 11.7186) radius 5.9032 clockwise from (-15.05, 17.1559) to (-13.5076, 17.5732)
  arc A19 centre (-1.224, -77.5099) radius 95.8732 clockwise from (-13.5076, 17.5732) to (-1.489, 18.363)
  arc A20 centre (1.6737, -77.5019) radius 95.8732 clockwise from (1.4087, 18.371) to (13.4315, 17.6476)
  arc A21 centre (12.7075, 11.789) radius 5.9032 clockwise from (13.4315, 17.6476) to (14.9761, 17.2389)
  arc A22 centre (8.9148, 2.6777) radius 15.7724 clockwise from (14.9761, 17.2389) to (17.3028, 16.0346)
  arc A23 centre (15.2309, 12.7354) radius 3.8959 clockwise from (17.3028, 16.0346) to (18.2456, 15.2031)
  arc A24 centre (-1.4655, -0.9318) radius 25.4728 clockwise from (18.2456, 15.2031) to (19.1999, 13.9613)
  arc A25 centre (14.4176, 10.5147) radius 5.8949 clockwise from (19.1999, 13.9613) to (20.0127, 12.3704)
  arc A26 centre (-8.1385, 3.034) radius 29.659 clockwise from (20.0127, 12.3704) to (21.1361, 7.7942)
  arc A27 centre (-50.8689, -3.9143) radius 72.9507 clockwise from (21.1361, 7.7942) to (21.8144, 2.3258)
  arc A28 centre (-55.8311, -4.3404) radius 77.9312 clockwise from (21.8144, 2.3258) to (21.8834, -10.1477)
  arc A29 centre (13.1472, -9.4949) radius 8.7605 clockwise from (21.8834, -10.1477) to (20.0813, -14.8488)
  arc A30 centre (17.0873, -12.5371) radius 3.7827 clockwise from (20.0813, -14.8488) to (19.0556, -15.7673)
  arc A31 centre (12.8825, -5.6366) radius 11.8633 clockwise from (19.0556, -15.7673) to (16.8008, -16.8342)
  arc A32 centre (13.133, -6.3524) radius 11.105 clockwise from (16.8008, -16.8342) to (15.1704, -17.2689)
  arc A33 centre (8.2784, 19.6584) radius 37.5649 clockwise from (15.1704, -17.2689) to (12.9514, -17.6147)
  arc A34 centre (0.0273, 85.4712) radius 103.8929 clockwise from (12.9514, -17.6147) to (6.9964, -18.1877)
  arc A35 centre (-10.7069, 1.2005) radius 18.2479 clockwise from (-15.8012, 18.7229) to (-11.5158, 19.4304)
  arc A36 centre (-12.2327, 6.4486) radius 12.7824 clockwise from (-19.4858, 16.974) to (-15.8012, 18.7229)
  arc A37 centre (-16.2941, 12.3424) radius 5.6248 clockwise from (-21.3014, 14.9047) to (-19.4858, 16.974)
  arc A38 centre (-6.3134, 7.2351) radius 16.8364 clockwise from (-22.3695, 12.3014) to (-21.3014, 14.9047)
  arc A39 centre (7.6057, 2.843) radius 31.432 clockwise from (-23.6781, 5.8921) to (-22.3695, 12.3014)
  arc A40 centre (312.3688, -26.8612) radius 337.6393 clockwise from (-24.373, -2.259) to (-23.6781, 5.8921)
  arc A41 centre (27.9737, -6.0834) radius 52.4862 clockwise from (-24.3555, -10.1404) to (-24.373, -2.259)
  arc A42 centre (-14.2774, -9.359) radius 10.1083 clockwise from (-24.1926, -11.3252) to (-24.3555, -10.1404)
  arc A43 centre (-12.4351, -8.9937) radius 11.9865 clockwise from (-22.4141, -15.6341) to (-24.1926, -11.3252)
  arc A44 centre (-19.0969, -13.4267) radius 3.9846 clockwise from (-21.4708, -16.6269) to (-22.4141, -15.6341)
  arc A45 centre (-14.7144, -7.5187) radius 11.3406 clockwise from (-17.105, -18.6044) to (-21.4708, -16.6269)
  arc A46 centre (-7.8992, 24.0836) radius 43.6694 clockwise from (-11.6229, -19.4267) to (-17.105, -18.6044)
  arc A47 centre (-1.7175, 96.317) radius 116.1669 clockwise from (-1.7175, -19.8498) to (-11.6229, -19.4267)
  arc A48 centre (1.2062, 96.3251) radius 116.1669 clockwise from (11.7513, -19.3621) to (1.8484, -19.84)
  arc A49 centre (7.7872, 24.127) radius 43.6694 clockwise from (17.2288, -18.5095) to (11.7513, -19.3621)
  arc A50 centre (14.7769, -7.4372) radius 11.3406 clockwise from (21.5836, -16.5079) to (17.2288, -18.5095)
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  point P143 (-24.2003, 0)
  point P1 (0, 0)
  point P144 (0, 0)
  point P147 (1.5038, 18.6297)
  point P201 (1.5038, 19.1297)
  point P146 (0.0038, 18.6297)
  point P149 (1.7038, 18.4297)
  point P151 (-1.6962, 18.4297)
  point P202 (1.9038, 19.1297)
  point P203 (-1.6962, 19.1297)
  point P204 (-1.8962, 19.1297)
  point P205 (0.0038, 19.8297)
  point P206 (0.003, 20.0296)
  point P207 (0.0038, 18.4297)
  point P208 (0.0038, 18.2297)
  point P245 (1.6962, -19.1297)
  point P246 (1.8962, -19.1297)
  point P247 (-0.0038, -18.4297)
  point P248 (-0.0038, -18.2297)
  point P285 (-22.3797, -0.187)
  point P286 (-22.1802, -0.201)
  point P287 (-22.9535, 1.6432)
  point P288 (-22.9395, 1.8427)
  point P301 (23.225, -1.697)
  point P302 (23.2389, -1.8965)
  point P303 (22.3847, 0.2845)
  point P304 (22.1852, 0.2706)
  coincident A40 P143
  horizontal L9
  horizontal L10
  coincident P1 P144
  vertical L11
  perpendicular L13 L15
  perpendicular L11 L16
  coincident P147 L11
  coincident P147 L15
  perpendicular L18 L19
  perpendicular L17 L20
  perpendicular L22 L23
  perpendicular L21 L24
  perpendicular L25 L28
  perpendicular L26 L27
  horizontal L29
  midpoint L11 P201
  perpendicular L7 L31
  perpendicular L56 L59
  dimension "d86" distance P146 P147 = 1.5
  dimension "d89" distance P149 P151 = 3.4
  dimension "d90" radius = 0.4
  dimension "d91" radius = 0.4
  dimension "d92" radius = 0.4
  dimension "d93" radius = 0.4
  dimension "d102" distance P201 P202 = 0.4
  dimension "d103" distance P203 P204 = 0.2
  dimension "d104" distance P205 P206 = 0.2
  dimension "d105" distance P207 P208 = 0.2
  dimension "d106" distance = 0.4
  dimension "d107" distance P245 P246 = 0.2
  dimension "d108" distance P247 P248 = 0.2
  dimension "d109" distance P285 P286 = 0.2
  dimension "d110" distance P287 P288 = 0.2
  dimension "d111" distance P301 P302 = 0.2
  dimension "d112" distance P303 P304 = 0.2
work_plane "Arbeitsebene3" AlongDistance 0
split "Teilen3" bodies "Honda_innen"
extrude "Extrusion21" cut sketch "Skizze11" + "Skizze10" blind -6
extrude "Extrusion22" add of existing geometry blind 1
move "Verschieben4"
extrude "Extrusion23" add sketch "Skizze11" + "Skizze10" blind -6
extrude "Extrusion24" cut sketch "Skizze11" against normal blind 9
move "Verschieben5"
extrude "Extrusion25" add of existing geometry blind 1
fillet "Abrundung5" radius 1.2
extrude "Extrusion26" cut of existing geometry blind -0.5
delete_face "Fläche löschen4"
extrude "Extrusion27" add of existing geometry blind 0.5
delete_face "Fläche löschen5"
delete_face "Fläche löschen6"
chamfer "Fase4" distance 3
extrude "Extrusion28" cut of existing geometry blind -0.5
delete_face "Fläche löschen7"
extrude "Extrusion29" cut of existing geometry blind -0.5
delete_face "Fläche löschen8"
extrude "Extrusion30" cut of existing geometry blind -0.5
delete_face "Fläche löschen9"
delete_face "Fläche löschen10"
delete_face "Fläche löschen11"
delete_face "Fläche löschen12"
delete_face "Fläche löschen13"
delete_face "Fläche löschen14"
delete_face "Fläche löschen15"
delete_face "Fläche löschen16"
work_plane "Arbeitsebene4" AlongDistance 0
split "Teilen4"
combine "Kombinieren3"
sketch "Skizze12" plane through (0, 0, -2) normal (0, 0, -1) x axis (1, 0, 0)
  line L1 (25.7237, 6.4452) -> (27.0548, 7.2137)
  line L2 (18.4436, 19.0548) -> (25.7237, 6.4452)
  line L3 (19.7747, 19.8233) -> (18.4436, 19.0548)
  line L4 (7.2801, -25.5) -> (-7.2801, -25.5)
  line L5 (7.2801, -27.037) -> (7.2801, -25.5)
  line L6 (-7.2801, -25.5) -> (-7.2801, -27.037)
  line L7 (-25.7237, 6.4452) -> (-18.4436, 19.0548)
  line L8 (-27.0548, 7.2137) -> (-25.7237, 6.4452)
  line L9 (-18.4436, 19.0548) -> (-19.7747, 19.8233)
  line L10 (-18.4436, -19.0548) -> (-25.7237, -6.4452)
  line L11 (-19.7747, -19.8233) -> (-18.4436, -19.0548)
  line L12 (-25.7237, -6.4452) -> (-27.0548, -7.2137)
  line L13 (7.2801, 25.5) -> (7.2801, 27.037)
  line L14 (-7.2801, 25.5) -> (7.2801, 25.5)
  line L15 (-7.2801, 27.037) -> (-7.2801, 25.5)
  line L16 (18.8766, -19.3048) -> (19.7747, -19.8233)
  line L17 (26.1567, -6.6952) -> (18.8766, -19.3048)
  line L18 (27.0548, -7.2137) -> (26.1567, -6.6952)
  line L19 (1.0962, -18.2303) -> (-1.1038, -18.2303)
  line L20 (1.8962, -19.2303) -> (1.8962, -19.0303)
  line L21 (-1.1038, -20.0303) -> (1.0962, -20.0303)
  line L22 (-1.9038, -19.0303) -> (-1.9038, -19.2303)
  line L23 (24.0472, -1.0881) -> (23.8938, 1.1065)
  line L24 (23.1055, -1.9559) -> (23.305, -1.942)
  line L25 (22.0982, 0.9809) -> (22.2516, -1.2137)
  line L26 (23.0399, 1.8488) -> (22.8404, 1.8348)
  line L27 (-22.2936, -1.1604) -> (-22.1402, 1.0343)
  line L28 (-23.347, -1.8887) -> (-23.1475, -1.9026)
  line L29 (-23.9358, 1.1598) -> (-24.0893, -1.0348)
  line L30 (-22.8824, 1.8881) -> (-23.0819, 1.9021)
  line L31 (1.0962, 20.0297) -> (-1.1038, 20.0297)
  line L32 (1.8962, 19.0297) -> (1.8962, 19.2297)
  line L33 (-1.1038, 18.2297) -> (1.0962, 18.2297)
  line L34 (-1.9038, 19.2297) -> (-1.9038, 19.0297)
  arc A1 centre (0, 0) radius 28 clockwise from (19.7747, 19.8233) to (27.0548, 7.2137)
  arc A2 centre (0, 0) radius 28 clockwise from (7.2801, -27.037) to (-7.2801, -27.037)
  arc A3 centre (0, 0) radius 28 clockwise from (-27.0548, 7.2137) to (-19.7747, 19.8233)
  arc A4 centre (0, 0) radius 28 clockwise from (-19.7747, -19.8233) to (-27.0548, -7.2137)
  arc A5 centre (0, 0) radius 28 clockwise from (-7.2801, 27.037) to (7.2801, 27.037)
  arc A6 centre (0, 0) radius 28 clockwise from (27.0548, -7.2137) to (19.7747, -19.8233)
  arc A7 centre (-1.1038, -19.0303) radius 0.8 clockwise from (-1.9038, -19.0303) to (-1.1038, -18.2303)
  arc A8 centre (1.0962, -19.0303) radius 0.8 clockwise from (1.0962, -18.2303) to (1.8962, -19.0303)
  arc A9 centre (1.0962, -19.2303) radius 0.8 clockwise from (1.8962, -19.2303) to (1.0962, -20.0303)
  arc A10 centre (-1.1038, -19.2303) radius 0.8 clockwise from (-1.1038, -20.0303) to (-1.9038, -19.2303)
  arc A11 centre (23.2492, -1.1439) radius 0.8 clockwise from (24.0472, -1.0881) to (23.305, -1.942)
  arc A12 centre (23.0497, -1.1579) radius 0.8 clockwise from (23.1055, -1.9559) to (22.2516, -1.2137)
  arc A13 centre (22.8962, 1.0368) radius 0.8 clockwise from (22.0982, 0.9809) to (22.8404, 1.8348)
  arc A14 centre (23.0957, 1.0507) radius 0.8 clockwise from (23.0399, 1.8488) to (23.8938, 1.1065)
  arc A15 centre (-23.0917, -1.1046) radius 0.8 clockwise from (-22.2936, -1.1604) to (-23.1475, -1.9026)
  arc A16 centre (-23.2912, -1.0906) radius 0.8 clockwise from (-23.347, -1.8887) to (-24.0893, -1.0348)
  arc A17 centre (-23.1377, 1.104) radius 0.8 clockwise from (-23.9358, 1.1598) to (-23.0819, 1.9021)
  arc A18 centre (-22.9382, 1.0901) radius 0.8 clockwise from (-22.8824, 1.8881) to (-22.1402, 1.0343)
  arc A19 centre (-1.1038, 19.2297) radius 0.8 clockwise from (-1.9038, 19.2297) to (-1.1038, 20.0297)
  arc A20 centre (1.0962, 19.2297) radius 0.8 clockwise from (1.0962, 20.0297) to (1.8962, 19.2297)
  arc A21 centre (1.0962, 19.0297) radius 0.8 clockwise from (1.8962, 19.0297) to (1.0962, 18.2297)
  arc A22 centre (-1.1038, 19.0297) radius 0.8 clockwise from (-1.1038, 18.2297) to (-1.9038, 19.0297)
  circle C1 centre (-12.3393, -11.7822) radius 1.6
  circle C2 centre (12.2528, -11.8501) radius 1.6
  circle C3 centre (-9.3758, 9.0032) radius 1.6
  circle C4 centre (9.4042, 8.9513) radius 1.6
  circle C5 centre (0, 0) radius 30
  circle C6 centre (0, 0) radius 25.0019
  circle C7 centre (0, 0) radius 28
  point P14 (-27.0548, 7.2137)
  concentric C5 C6
  concentric C5 C7
  coincident P14 C7
extrude "Extrusion31" add of existing geometry blind 0.5
extrude "Extrusion32" cut sketch "Skizze12" profile of A1 L1 L2 L3 L4 L5 L6 L7 L8 L9 L10 L11 L12 L13 L14 L15 L16 L17 L18 A7 L19 A8 L20 A9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 against normal blind 2.5
extrude "Extrusion33" add of existing geometry to an object
split "Teilen5"
extrude "Extrusion34" cut of existing geometry blind -3
move "Verschieben12"
move "Verschieben13"
move "Verschieben14"
move "Verschieben15"
move "Verschieben16"
move "Verschieben17"
sketch "Skizze13" plane through (0, 0, 0.5) normal (0, 0, -1) x axis (1, 0, 0)
  line L1 (-1.1038, 18.2297) -> (1.0962, 18.2297)
  line L2 (-1.9038, 19.2297) -> (-1.9038, 19.0297)
  line L3 (1.0962, 20.0297) -> (-1.1038, 20.0297)
  line L4 (1.8962, 19.0297) -> (1.8962, 19.2297)
  line L5 (23.1055, -1.9559) -> (23.305, -1.942)
  line L6 (22.0982, 0.9809) -> (22.2516, -1.2137)
  line L7 (23.0399, 1.8488) -> (22.8404, 1.8348)
  line L8 (24.0472, -1.0881) -> (23.8938, 1.1065)
  line L9 (-1.1038, -20.0303) -> (1.0962, -20.0303)
  line L10 (-1.9038, -19.0303) -> (-1.9038, -19.2303)
  line L11 (1.0962, -18.2303) -> (-1.1038, -18.2303)
  line L12 (1.8962, -19.2303) -> (1.8962, -19.0303)
  line L13 (-23.347, -1.8887) -> (-23.1475, -1.9026)
  line L14 (-23.9358, 1.1598) -> (-24.0893, -1.0348)
  line L15 (-22.8824, 1.8881) -> (-23.0819, 1.9021)
  line L16 (-22.2936, -1.1604) -> (-22.1402, 1.0343)
  circle C1 centre (0, 0) radius 30
  circle C2 centre (9.4042, 8.9513) radius 1.6
  arc A1 centre (1.0962, 19.0297) radius 0.8 clockwise from (1.8962, 19.0297) to (1.0962, 18.2297)
  arc A2 centre (-1.1038, 19.0297) radius 0.8 clockwise from (-1.1038, 18.2297) to (-1.9038, 19.0297)
  arc A3 centre (-1.1038, 19.2297) radius 0.8 clockwise from (-1.9038, 19.2297) to (-1.1038, 20.0297)
  arc A4 centre (1.0962, 19.2297) radius 0.8 clockwise from (1.0962, 20.0297) to (1.8962, 19.2297)
  circle C3 centre (-12.3393, -11.7822) radius 1.6
  circle C4 centre (12.2528, -11.8501) radius 1.6
  arc A5 centre (23.2492, -1.1439) radius 0.8 clockwise from (24.0472, -1.0881) to (23.305, -1.942)
  arc A6 centre (23.0497, -1.1579) radius 0.8 clockwise from (23.1055, -1.9559) to (22.2516, -1.2137)
  arc A7 centre (22.8962, 1.0368) radius 0.8 clockwise from (22.0982, 0.9809) to (22.8404, 1.8348)
  arc A8 centre (23.0957, 1.0507) radius 0.8 clockwise from (23.0399, 1.8488) to (23.8938, 1.1065)
  arc A9 centre (1.0962, -19.2303) radius 0.8 clockwise from (1.8962, -19.2303) to (1.0962, -20.0303)
  arc A10 centre (-1.1038, -19.2303) radius 0.8 clockwise from (-1.1038, -20.0303) to (-1.9038, -19.2303)
  arc A11 centre (-1.1038, -19.0303) radius 0.8 clockwise from (-1.9038, -19.0303) to (-1.1038, -18.2303)
  arc A12 centre (1.0962, -19.0303) radius 0.8 clockwise from (1.0962, -18.2303) to (1.8962, -19.0303)
  circle C5 centre (-9.3758, 9.0032) radius 1.6
  arc A13 centre (-23.0917, -1.1046) radius 0.8 clockwise from (-22.2936, -1.1604) to (-23.1475, -1.9026)
  arc A14 centre (-23.2912, -1.0906) radius 0.8 clockwise from (-23.347, -1.8887) to (-24.0893, -1.0348)
  arc A15 centre (-23.1377, 1.104) radius 0.8 clockwise from (-23.9358, 1.1598) to (-23.0819, 1.9021)
  arc A16 centre (-22.9382, 1.0901) radius 0.8 clockwise from (-22.8824, 1.8881) to (-22.1402, 1.0343)
  circle C6 centre (0, 0) radius 27.0356
  circle C7 centre (0, 0) radius 25.5588
  point P56 (18.9087, -19.3233)
  point P58 (17.5776, -18.5548)
  concentric C1 C6
  coincident C6 P56
  concentric C1 C7
  coincident C7 P58
extrude "Extrusion35" add sketch "Skizze13" profile of C1 C6 C7 along normal blind 2
sketch "Skizze14" plane through (0, 0, 3) normal (0, 0, 1) x axis (-1, 0, 0)
  line L1 (1.9038, -19.2303) -> (1.9038, -19.0303)
  line L2 (-1.0962, -20.0303) -> (1.1038, -20.0303)
  line L3 (-1.8962, -19.0303) -> (-1.8962, -19.2303)
  line L4 (1.1038, -18.2303) -> (-1.0962, -18.2303)
  line L5 (-23.8938, 1.1065) -> (-24.0472, -1.0881)
  line L6 (-22.8404, 1.8348) -> (-23.0399, 1.8488)
  line L7 (-22.2516, -1.2137) -> (-22.0982, 0.9809)
  line L8 (-23.305, -1.942) -> (-23.1055, -1.9559)
  line L9 (22.1402, 1.0343) -> (22.2936, -1.1604)
  line L10 (23.0819, 1.9021) -> (22.8824, 1.8881)
  line L11 (24.0893, -1.0348) -> (23.9358, 1.1598)
  line L12 (23.1475, -1.9026) -> (23.347, -1.8887)
  line L13 (1.9038, 19.0297) -> (1.9038, 19.2297)
  line L14 (-1.0962, 18.2297) -> (1.1038, 18.2297)
  line L15 (-1.8962, 19.2297) -> (-1.8962, 19.0297)
  line L16 (1.1038, 20.0297) -> (-1.0962, 20.0297)
  arc A1 centre (1.1038, -19.0303) radius 0.8 clockwise from (1.1038, -18.2303) to (1.9038, -19.0303)
  arc A2 centre (1.1038, -19.2303) radius 0.8 clockwise from (1.9038, -19.2303) to (1.1038, -20.0303)
  arc A3 centre (-1.0962, -19.2303) radius 0.8 clockwise from (-1.0962, -20.0303) to (-1.8962, -19.2303)
  arc A4 centre (-1.0962, -19.0303) radius 0.8 clockwise from (-1.8962, -19.0303) to (-1.0962, -18.2303)
  arc A5 centre (-23.0957, 1.0507) radius 0.8 clockwise from (-23.8938, 1.1065) to (-23.0399, 1.8488)
  arc A6 centre (-22.8962, 1.0368) radius 0.8 clockwise from (-22.8404, 1.8348) to (-22.0982, 0.9809)
  arc A7 centre (-23.0497, -1.1579) radius 0.8 clockwise from (-22.2516, -1.2137) to (-23.1055, -1.9559)
  arc A8 centre (-23.2492, -1.1439) radius 0.8 clockwise from (-23.305, -1.942) to (-24.0472, -1.0881)
  arc A9 centre (22.9382, 1.0901) radius 0.8 clockwise from (22.1402, 1.0343) to (22.8824, 1.8881)
  arc A10 centre (23.1377, 1.104) radius 0.8 clockwise from (23.0819, 1.9021) to (23.9358, 1.1598)
  arc A11 centre (23.2912, -1.0906) radius 0.8 clockwise from (24.0893, -1.0348) to (23.347, -1.8887)
  arc A12 centre (23.0917, -1.1046) radius 0.8 clockwise from (23.1475, -1.9026) to (22.2936, -1.1604)
  arc A13 centre (1.1038, 19.2297) radius 0.8 clockwise from (1.1038, 20.0297) to (1.9038, 19.2297)
  arc A14 centre (1.1038, 19.0297) radius 0.8 clockwise from (1.9038, 19.0297) to (1.1038, 18.2297)
  arc A15 centre (-1.0962, 19.0297) radius 0.8 clockwise from (-1.0962, 18.2297) to (-1.8962, 19.0297)
  arc A16 centre (-1.0962, 19.2297) radius 0.8 clockwise from (-1.8962, 19.2297) to (-1.0962, 20.0297)
  circle C1 centre (12.3393, -11.7822) radius 1.6
  circle C2 centre (-12.2528, -11.8501) radius 1.6
  circle C3 centre (9.3758, 9.0032) radius 1.6
  circle C4 centre (-9.4042, 8.9513) radius 1.6
  circle C5 centre (0, 0) radius 30
  circle C6 centre (0, 0) radius 29.8
  point P1 (0, 0)
  point P55 (0, 0)
  coincident P1 P55
  dimension "d142" diameter C6 = 59.6
extrude "Extrusion36" cut sketch "Skizze14" profile of C5 C6 against normal blind 12
extrude "Extrusion37" add of existing geometry blind 1
extrude "Extrusion38" add of existing geometry blind 1
extrude "Extrusion39" add of existing geometry blind 1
